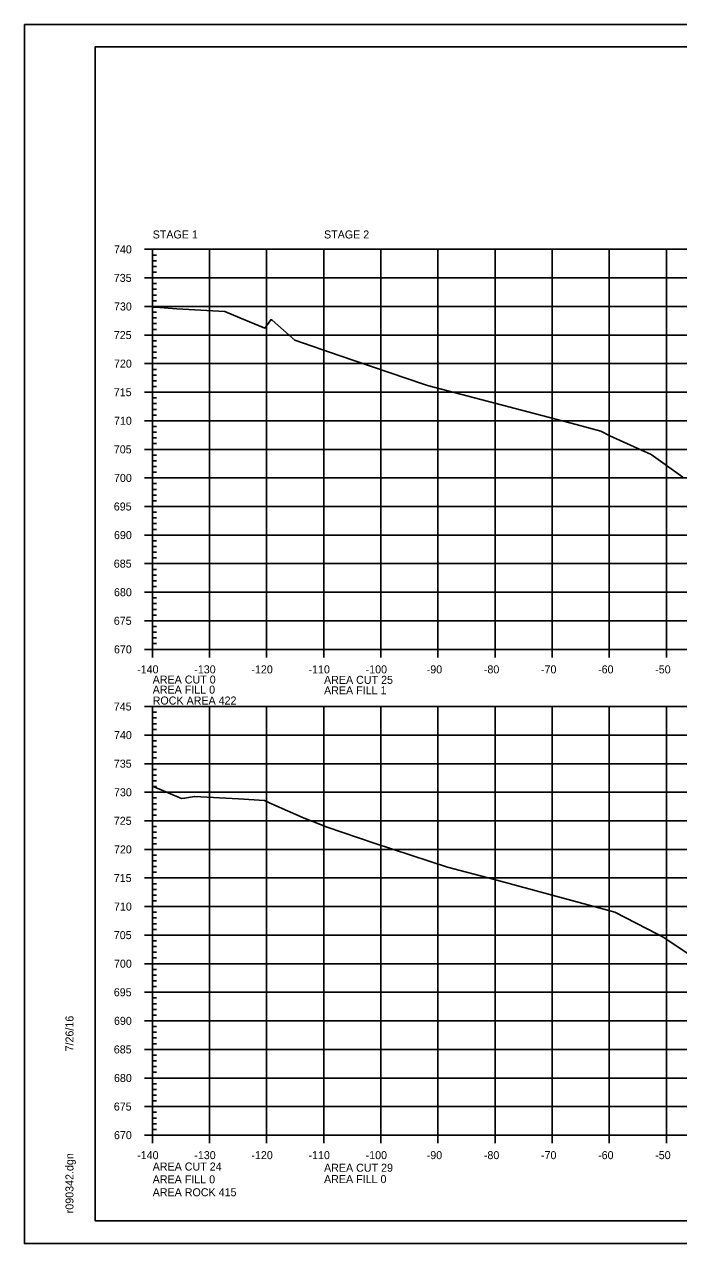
# Model space of a CAD drawing. Extents: x 1370515 to 1370849, y 383299 to 386073.
# Drawn here: x 1370515.4 to 1370629.9, y 383726.1 to 383939.4 of the extents above; entities that cross this region are included whole.
import ezdxf

# ---------------------------------------------------------------- set-up
doc = ezdxf.new("R2010")
doc.units = 0
for name, color, linetype in [('R_Axis', 7, 'Continuous'), ('R_Axis Annot', 7, 'Continuous'), ('R_Border', 7, 'Continuous'), ('R_Exist Surface', 7, 'Continuous'), ('R_Grid', 7, 'Continuous'), ('R_No Plot', 7, 'Continuous')]:
    doc.layers.add(name, color=color, linetype=linetype)

msp = doc.modelspace()

# ---------------------------------------------------------------- linework, layer by layer
at = {"layer": 'R_Axis'}
for p, q in [((1370536.4, 383900.08), (1370539.2, 383900.08)), ((1370537.8, 383830.08), (1370537.8, 383900.08)), ((1370537.8, 383899.08), (1370538.5, 383899.08)), ((1370537.8, 383898.08), (1370538.5, 383898.08)), ((1370537.8, 383897.08), (1370538.5, 383897.08)), ((1370536.4, 383895.08), (1370539.2, 383895.08)), ((1370537.8, 383896.08), (1370538.5, 383896.08)), ((1370537.8, 383894.08), (1370538.5, 383894.08)), ((1370537.8, 383893.08), (1370538.5, 383893.08)), ((1370537.8, 383892.08), (1370538.5, 383892.08)), ((1370537.8, 383891.08), (1370538.5, 383891.08)), ((1370536.4, 383890.08), (1370539.2, 383890.08)), ((1370537.8, 383889.08), (1370538.5, 383889.08)), ((1370537.8, 383888.08), (1370538.5, 383888.08)), ((1370537.8, 383887.08), (1370538.5, 383887.08)), ((1370537.8, 383886.08), (1370538.5, 383886.08)), ((1370536.4, 383885.08), (1370539.2, 383885.08)), ((1370537.8, 383884.08), (1370538.5, 383884.08)), ((1370537.8, 383883.08), (1370538.5, 383883.08)), ((1370537.8, 383882.08), (1370538.5, 383882.08)), ((1370536.4, 383880.08), (1370539.2, 383880.08)), ((1370537.8, 383881.08), (1370538.5, 383881.08)), ((1370537.8, 383879.08), (1370538.5, 383879.08)), ((1370537.8, 383878.08), (1370538.5, 383878.08)), ((1370537.8, 383877.08), (1370538.5, 383877.08)), ((1370537.8, 383876.08), (1370538.5, 383876.08)), ((1370536.4, 383875.08), (1370539.2, 383875.08)), ((1370537.8, 383874.08), (1370538.5, 383874.08)), ((1370537.8, 383873.08), (1370538.5, 383873.08)), ((1370537.8, 383872.08), (1370538.5, 383872.08)), ((1370536.4, 383870.08), (1370539.2, 383870.08)), ((1370537.8, 383871.08), (1370538.5, 383871.08)), ((1370537.8, 383869.08), (1370538.5, 383869.08)), ((1370537.8, 383868.08), (1370538.5, 383868.08)), ((1370537.8, 383867.08), (1370538.5, 383867.08)), ((1370536.4, 383865.08), (1370539.2, 383865.08)), ((1370537.8, 383866.08), (1370538.5, 383866.08)), ((1370537.8, 383864.08), (1370538.5, 383864.08)), ((1370537.8, 383863.08), (1370538.5, 383863.08)), ((1370537.8, 383862.08), (1370538.5, 383862.08)), ((1370537.8, 383861.08), (1370538.5, 383861.08)), ((1370536.4, 383860.08), (1370539.2, 383860.08)), ((1370537.8, 383859.08), (1370538.5, 383859.08)), ((1370537.8, 383858.08), (1370538.5, 383858.08)), ((1370537.8, 383857.08), (1370538.5, 383857.08)), ((1370536.4, 383855.08), (1370539.2, 383855.08)), ((1370537.8, 383856.08), (1370538.5, 383856.08)), ((1370537.8, 383854.08), (1370538.5, 383854.08)), ((1370537.8, 383853.08), (1370538.5, 383853.08)), ((1370537.8, 383852.08), (1370538.5, 383852.08)), ((1370536.4, 383850.08), (1370539.2, 383850.08)), ((1370537.8, 383851.08), (1370538.5, 383851.08)), ((1370537.8, 383849.08), (1370538.5, 383849.08)), ((1370537.8, 383848.08), (1370538.5, 383848.08)), ((1370537.8, 383847.08), (1370538.5, 383847.08)), ((1370537.8, 383846.08), (1370538.5, 383846.08)), ((1370536.4, 383845.08), (1370539.2, 383845.08)), ((1370537.8, 383844.08), (1370538.5, 383844.08)), ((1370537.8, 383843.08), (1370538.5, 383843.08)), ((1370537.8, 383842.08), (1370538.5, 383842.08)), ((1370536.4, 383840.08), (1370539.2, 383840.08)), ((1370537.8, 383841.08), (1370538.5, 383841.08)), ((1370537.8, 383839.08), (1370538.5, 383839.08)), ((1370537.8, 383838.08), (1370538.5, 383838.08)), ((1370537.8, 383837.08), (1370538.5, 383837.08)), ((1370536.4, 383835.08), (1370539.2, 383835.08)), ((1370537.8, 383836.08), (1370538.5, 383836.08)), ((1370537.8, 383834.08), (1370538.5, 383834.08)), ((1370537.8, 383833.08), (1370538.5, 383833.08)), ((1370537.8, 383832.08), (1370538.5, 383832.08)), ((1370537.8, 383828.68), (1370537.8, 383831.48)), ((1370537.8, 383831.08), (1370538.5, 383831.08)), ((1370547.8, 383828.68), (1370547.8, 383831.48)), ((1370557.8, 383828.68), (1370557.8, 383831.48)), ((1370567.8, 383828.68), (1370567.8, 383831.48)), ((1370577.8, 383828.68), (1370577.8, 383831.48)), ((1370587.8, 383828.68), (1370587.8, 383831.48)), ((1370597.8, 383828.68), (1370597.8, 383831.48)), ((1370607.8, 383828.68), (1370607.8, 383831.48)), ((1370617.8, 383828.68), (1370617.8, 383831.48)), ((1370627.8, 383828.68), (1370627.8, 383831.48)), ((1370536.4, 383830.08), (1370539.2, 383830.08)), ((1370537.8, 383830.08), (1370817.8, 383830.08)), ((1370536.4, 383820.08), (1370539.2, 383820.08)), ((1370537.8, 383745.08), (1370537.8, 383820.08)), ((1370537.8, 383819.08), (1370538.5, 383819.08)), ((1370537.8, 383818.08), (1370538.5, 383818.08)), ((1370537.8, 383817.08), (1370538.5, 383817.08)), ((1370537.8, 383816.08), (1370538.5, 383816.08)), ((1370536.4, 383815.08), (1370539.2, 383815.08)), ((1370537.8, 383814.08), (1370538.5, 383814.08)), ((1370537.8, 383813.08), (1370538.5, 383813.08)), ((1370537.8, 383812.08), (1370538.5, 383812.08)), ((1370536.4, 383810.08), (1370539.2, 383810.08)), ((1370537.8, 383811.08), (1370538.5, 383811.08)), ((1370537.8, 383809.08), (1370538.5, 383809.08)), ((1370537.8, 383808.08), (1370538.5, 383808.08)), ((1370536.4, 383805.08), (1370539.2, 383805.08)), ((1370537.8, 383807.08), (1370538.5, 383807.08)), ((1370537.8, 383806.08), (1370538.5, 383806.08)), ((1370537.8, 383804.08), (1370538.5, 383804.08)), ((1370537.8, 383803.08), (1370538.5, 383803.08)), ((1370537.8, 383802.08), (1370538.5, 383802.08)), ((1370537.8, 383801.08), (1370538.5, 383801.08)), ((1370536.4, 383800.08), (1370539.2, 383800.08)), ((1370537.8, 383799.08), (1370538.5, 383799.08)), ((1370537.8, 383798.08), (1370538.5, 383798.08)), ((1370537.8, 383797.08), (1370538.5, 383797.08)), ((1370536.4, 383795.08), (1370539.2, 383795.08)), ((1370537.8, 383796.08), (1370538.5, 383796.08)), ((1370537.8, 383794.08), (1370538.5, 383794.08)), ((1370537.8, 383793.08), (1370538.5, 383793.08)), ((1370536.4, 383790.08), (1370539.2, 383790.08)), ((1370537.8, 383792.08), (1370538.5, 383792.08)), ((1370537.8, 383791.08), (1370538.5, 383791.08)), ((1370537.8, 383789.08), (1370538.5, 383789.08)), ((1370537.8, 383788.08), (1370538.5, 383788.08)), ((1370537.8, 383787.08), (1370538.5, 383787.08)), ((1370537.8, 383786.08), (1370538.5, 383786.08)), ((1370536.4, 383785.08), (1370539.2, 383785.08)), ((1370537.8, 383784.08), (1370538.5, 383784.08)), ((1370537.8, 383783.08), (1370538.5, 383783.08)), ((1370537.8, 383782.08), (1370538.5, 383782.08)), ((1370536.4, 383780.08), (1370539.2, 383780.08)), ((1370537.8, 383781.08), (1370538.5, 383781.08)), ((1370537.8, 383779.08), (1370538.5, 383779.08)), ((1370537.8, 383778.08), (1370538.5, 383778.08)), ((1370537.8, 383777.08), (1370538.5, 383777.08)), ((1370537.8, 383776.08), (1370538.5, 383776.08)), ((1370536.4, 383775.08), (1370539.2, 383775.08)), ((1370537.8, 383774.08), (1370538.5, 383774.08)), ((1370537.8, 383773.08), (1370538.5, 383773.08)), ((1370537.8, 383772.08), (1370538.5, 383772.08)), ((1370537.8, 383771.08), (1370538.5, 383771.08)), ((1370536.4, 383770.08), (1370539.2, 383770.08)), ((1370537.8, 383769.08), (1370538.5, 383769.08)), ((1370537.8, 383768.08), (1370538.5, 383768.08)), ((1370537.8, 383767.08), (1370538.5, 383767.08)), ((1370536.4, 383765.08), (1370539.2, 383765.08)), ((1370537.8, 383766.08), (1370538.5, 383766.08)), ((1370537.8, 383764.08), (1370538.5, 383764.08)), ((1370537.8, 383763.08), (1370538.5, 383763.08)), ((1370537.8, 383762.08), (1370538.5, 383762.08)), ((1370537.8, 383761.08), (1370538.5, 383761.08)), ((1370536.4, 383760.08), (1370539.2, 383760.08)), ((1370537.8, 383759.08), (1370538.5, 383759.08)), ((1370537.8, 383758.08), (1370538.5, 383758.08)), ((1370537.8, 383757.08), (1370538.5, 383757.08)), ((1370537.8, 383756.08), (1370538.5, 383756.08)), ((1370536.4, 383755.08), (1370539.2, 383755.08)), ((1370537.8, 383754.08), (1370538.5, 383754.08)), ((1370537.8, 383753.08), (1370538.5, 383753.08)), ((1370537.8, 383752.08), (1370538.5, 383752.08)), ((1370536.4, 383750.08), (1370539.2, 383750.08)), ((1370537.8, 383751.08), (1370538.5, 383751.08)), ((1370537.8, 383749.08), (1370538.5, 383749.08)), ((1370537.8, 383748.08), (1370538.5, 383748.08)), ((1370537.8, 383747.08), (1370538.5, 383747.08)), ((1370537.8, 383743.68), (1370537.8, 383746.48)), ((1370537.8, 383746.08), (1370538.5, 383746.08)), ((1370547.8, 383743.68), (1370547.8, 383746.48)), ((1370557.8, 383743.68), (1370557.8, 383746.48)), ((1370567.8, 383743.68), (1370567.8, 383746.48)), ((1370577.8, 383743.68), (1370577.8, 383746.48)), ((1370587.8, 383743.68), (1370587.8, 383746.48)), ((1370597.8, 383743.68), (1370597.8, 383746.48)), ((1370607.8, 383743.68), (1370607.8, 383746.48)), ((1370617.8, 383743.68), (1370617.8, 383746.48)), ((1370627.8, 383743.68), (1370627.8, 383746.48)), ((1370536.4, 383745.08), (1370539.2, 383745.08)), ((1370537.8, 383745.08), (1370817.8, 383745.08))]:
    msp.add_line(p, q, dxfattribs=at)
at = {"layer": 'R_Border'}
for p, q in [((1370527.8, 383935.54), (1370843.98, 383935.54)), ((1370527.8, 383730.08), (1370527.8, 383935.54)), ((1370527.8, 383730.08), (1370527.8, 383730.08)), ((1370843.98, 383730.08), (1370527.8, 383730.08))]:
    msp.add_line(p, q, dxfattribs=at)
at = {"layer": 'R_Exist Surface'}
for points in [[(1370537.8, 383889.88), (1370538.35, 383889.94), (1370542.08, 383889.69), (1370550.52, 383889.2), (1370553.1, 383888.09), (1370557.51, 383886.29), (1370558.54, 383887.76), (1370558.62, 383887.78), (1370558.76, 383887.69), (1370562.72, 383884.16), (1370570.48, 383881.51), (1370585.27, 383876.49), (1370585.98, 383876.26), (1370611.98, 383869.45), (1370616.35, 383868.26), (1370617.89, 383867.47), (1370625.13, 383864.18), (1370630.65, 383860.24)], [(1370537.8, 383806.13), (1370542.88, 383803.96), (1370543.45, 383804.02), (1370545.17, 383804.35), (1370552.9, 383803.9), (1370557.42, 383803.64), (1370558.52, 383803.13), (1370564.39, 383800.55), (1370565.9, 383799.99), (1370568.4, 383798.98), (1370576.66, 383796.18), (1370589.49, 383791.97), (1370597.5, 383789.87), (1370618.76, 383784.11), (1370626.23, 383780.24), (1370626.95, 383779.92), (1370627.5, 383779.53), (1370633.21, 383775.76)]]:
    msp.add_lwpolyline(points, dxfattribs=at)
at = {"layer": 'R_Grid'}
for p, q in [((1370537.8, 383900.08), (1370817.8, 383900.08)), ((1370537.8, 383830.08), (1370537.8, 383900.08)), ((1370547.8, 383830.08), (1370547.8, 383900.08)), ((1370557.8, 383830.08), (1370557.8, 383900.08)), ((1370567.8, 383830.08), (1370567.8, 383900.08)), ((1370577.8, 383830.08), (1370577.8, 383900.08)), ((1370587.8, 383830.08), (1370587.8, 383900.08)), ((1370597.8, 383830.08), (1370597.8, 383900.08)), ((1370607.8, 383830.08), (1370607.8, 383900.08)), ((1370617.8, 383830.08), (1370617.8, 383900.08)), ((1370627.8, 383830.08), (1370627.8, 383900.08)), ((1370537.8, 383895.08), (1370817.8, 383895.08)), ((1370537.8, 383890.08), (1370817.8, 383890.08)), ((1370537.8, 383885.08), (1370817.8, 383885.08)), ((1370537.8, 383880.08), (1370817.8, 383880.08)), ((1370537.8, 383875.08), (1370817.8, 383875.08)), ((1370537.8, 383870.08), (1370817.8, 383870.08)), ((1370537.8, 383865.08), (1370817.8, 383865.08)), ((1370537.8, 383860.08), (1370817.8, 383860.08)), ((1370537.8, 383855.08), (1370817.8, 383855.08)), ((1370537.8, 383850.08), (1370817.8, 383850.08)), ((1370537.8, 383845.08), (1370817.8, 383845.08)), ((1370537.8, 383840.08), (1370817.8, 383840.08)), ((1370537.8, 383835.08), (1370817.8, 383835.08)), ((1370537.8, 383830.08), (1370817.8, 383830.08)), ((1370537.8, 383820.08), (1370817.8, 383820.08)), ((1370537.8, 383745.08), (1370537.8, 383820.08)), ((1370547.8, 383745.08), (1370547.8, 383820.08)), ((1370557.8, 383745.08), (1370557.8, 383820.08)), ((1370567.8, 383745.08), (1370567.8, 383820.08)), ((1370577.8, 383745.08), (1370577.8, 383820.08)), ((1370587.8, 383745.08), (1370587.8, 383820.08)), ((1370597.8, 383745.08), (1370597.8, 383820.08)), ((1370607.8, 383745.08), (1370607.8, 383820.08)), ((1370617.8, 383745.08), (1370617.8, 383820.08)), ((1370627.8, 383745.08), (1370627.8, 383820.08)), ((1370537.8, 383815.08), (1370817.8, 383815.08)), ((1370537.8, 383810.08), (1370817.8, 383810.08)), ((1370537.8, 383805.08), (1370817.8, 383805.08)), ((1370537.8, 383800.08), (1370817.8, 383800.08)), ((1370537.8, 383795.08), (1370817.8, 383795.08)), ((1370537.8, 383790.08), (1370817.8, 383790.08)), ((1370537.8, 383785.08), (1370817.8, 383785.08)), ((1370537.8, 383780.08), (1370817.8, 383780.08)), ((1370537.8, 383775.08), (1370817.8, 383775.08)), ((1370537.8, 383770.08), (1370817.8, 383770.08)), ((1370537.8, 383765.08), (1370817.8, 383765.08)), ((1370537.8, 383760.08), (1370817.8, 383760.08)), ((1370537.8, 383755.08), (1370817.8, 383755.08)), ((1370537.8, 383750.08), (1370817.8, 383750.08)), ((1370537.8, 383745.08), (1370817.8, 383745.08))]:
    msp.add_line(p, q, dxfattribs=at)
at = {"layer": 'R_No Plot'}
for p, q in [((1370515.4, 383939.44), (1370848.73, 383939.44)), ((1370515.4, 383726.11), (1370848.73, 383726.11))]:
    msp.add_line(p, q, dxfattribs=at)
for points in [[(1370515.39, 383939.44), (1370848.73, 383939.44), (1370848.73, 383726.1), (1370515.39, 383726.1)], [(1370761.72, 383935.54), (1370761.72, 383925.66), (1370797.45, 383925.66), (1370797.45, 383922.74), (1370820.65, 383922.74), (1370820.65, 383899.53), (1370843.98, 383899.53), (1370843.98, 383730.08), (1370527.8, 383730.08), (1370527.8, 383935.54)]]:
    msp.add_lwpolyline(points, close=True, dxfattribs=at)

# ---------------------------------------------------------------- texts
at = {"layer": 'R_Axis'}
for p in [(1370537.8, 383830.08), (1370537.8, 383745.08)]:
    msp.add_text('-', height=0.0001, dxfattribs=at).set_placement(p)
at = {"layer": 'R_Axis Annot'}
for s, p in [('STAGE 1', (1370537.86, 383901.98)), ('STAGE 2', (1370567.86, 383901.98)), ('740', (1370531.08, 383899.38)), ('735', (1370531.05, 383894.38)), ('730', (1370531.08, 383889.38)), ('725', (1370531.05, 383884.38)), ('720', (1370531.08, 383879.38)), ('715', (1370531.05, 383874.38)), ('710', (1370531.08, 383869.38)), ('705', (1370531.05, 383864.38)), ('700', (1370531.08, 383859.38)), ('695', (1370531.05, 383854.38)), ('690', (1370531.08, 383849.38)), ('685', (1370531.05, 383844.38)), ('680', (1370531.08, 383839.38)), ('675', (1370531.05, 383834.38)), ('670', (1370531.08, 383829.38)), ('-140', (1370535.14, 383825.88)), ('-130', (1370545.14, 383825.88)), ('-120', (1370555.14, 383825.88)), ('-110', (1370565.14, 383825.88)), ('-100', (1370575.14, 383825.88)), ('-90', (1370585.84, 383825.88)), ('-80', (1370595.84, 383825.88)), ('-70', (1370605.84, 383825.88)), ('-60', (1370615.84, 383825.88)), ('-50', (1370625.84, 383825.88)), ('AREA CUT 0', (1370537.86, 383824.1)), ('AREA CUT 25', (1370567.86, 383824.05)), ('AREA FILL 0', (1370537.86, 383822.34)), ('AREA FILL 1', (1370567.86, 383822.21)), ('745', (1370531.05, 383819.38)), ('ROCK AREA 422', (1370537.86, 383820.43)), ('740', (1370531.08, 383814.38)), ('735', (1370531.05, 383809.38)), ('730', (1370531.08, 383804.38)), ('725', (1370531.05, 383799.38)), ('720', (1370531.08, 383794.38)), ('715', (1370531.05, 383789.38)), ('710', (1370531.08, 383784.38)), ('705', (1370531.05, 383779.38)), ('700', (1370531.08, 383774.38)), ('695', (1370531.05, 383769.38)), ('690', (1370531.08, 383764.38)), ('685', (1370531.05, 383759.38)), ('680', (1370531.08, 383754.38)), ('675', (1370531.05, 383749.38)), ('670', (1370531.08, 383744.38)), ('-140', (1370535.14, 383740.88)), ('-130', (1370545.14, 383740.88)), ('-120', (1370555.14, 383740.88)), ('-110', (1370565.14, 383740.88)), ('-100', (1370575.14, 383740.88)), ('-90', (1370585.84, 383740.88)), ('-80', (1370595.84, 383740.88)), ('-70', (1370605.84, 383740.88)), ('-60', (1370615.84, 383740.88)), ('-50', (1370625.84, 383740.88)), ('AREA CUT 24', (1370537.86, 383738.89)), ('AREA CUT 29', (1370567.86, 383738.68)), ('AREA FILL 0', (1370537.86, 383736.65)), ('AREA FILL 0', (1370567.86, 383736.69)), ('AREA ROCK 415', (1370537.86, 383734.39))]:
    msp.add_text(s, height=1.4, dxfattribs=at).set_placement(p)
at = {"layer": 'R_Border'}
for s, p in [('7/26/16', (1370523.99, 383759.73)), ('r090342.dgn', (1370523.99, 383731.41))]:
    msp.add_text(s, height=1.4, rotation=90, dxfattribs=at).set_placement(p)
at = {"layer": 'R_No Plot'}
for p in [(1370538.31, 383889.89), (1370550.48, 383889.15), (1370557.46, 383886.24), (1370558.58, 383887.73), (1370562.68, 383884.11), (1370585.94, 383876.21), (1370616.31, 383868.21), (1370625.09, 383864.13), (1370542.84, 383803.91), (1370545.13, 383804.3), (1370557.38, 383803.59), (1370564.35, 383800.5), (1370568.36, 383798.93), (1370589.45, 383791.92), (1370618.72, 383784.06), (1370626.91, 383779.87)]:
    msp.add_text('+', height=0.1, dxfattribs=at).set_placement(p)

doc.saveas('drawing.dxf')
